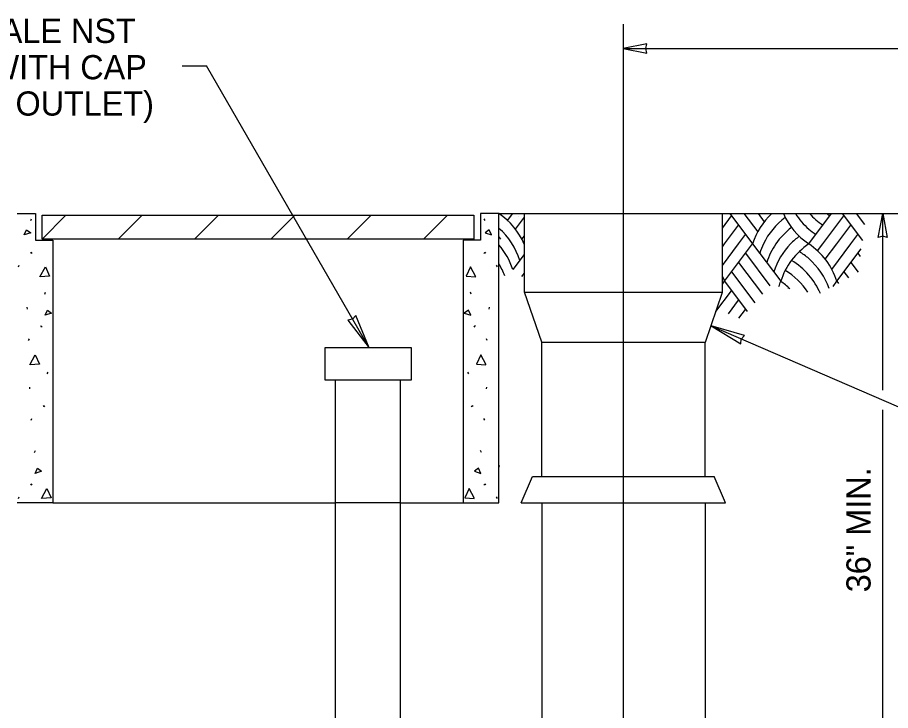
# Model space of a CAD drawing. Extents: x 99862 to 103151, y 99999 to 102075.
# Drawn here: x 100383 to 100960, y 100610 to 101068 of the extents above; entities that cross this region are included whole.
import ezdxf

# ---------------------------------------------------------------- set-up
doc = ezdxf.new("R2010")
doc.units = 0
for name, color, linetype in [('Level 1', 7, 'Continuous'), ('Level 10', 7, 'Continuous'), ('Level 13', 7, 'Continuous'), ('Level 15', 7, 'Continuous'), ('Level 17', 7, 'Continuous'), ('Level 18', 7, 'Continuous'), ('Level 20', 7, 'Continuous'), ('Level 3', 7, 'Continuous'), ('Level 6', 7, 'Continuous')]:
    doc.layers.add(name, color=color, linetype=linetype)

msp = doc.modelspace()

# ---------------------------------------------------------------- linework, layer by layer
at = {"layer": 'Level 1'}
for p, q in [((100391.62, 100933.79), (100392.18, 100935.05)), ((100399.05, 100921.6), (100399.05, 100937.39)), ((100399.05, 100937.39), (100684.58, 100937.39)), ((100684.58, 100937.39), (100684.58, 100921.6)), ((100692.01, 100933.79), (100691.45, 100935.05)), ((100684.58, 100921.6), (100399.05, 100921.6)), ((100391.44, 100913.04), (100391.85, 100912.31)), ((100391.85, 100912.75), (100392.43, 100912.06)), ((100691.78, 100912.75), (100691.2, 100912.06)), ((100692.19, 100913.04), (100691.78, 100912.31)), ((100383.49, 100903.21), (100384.05, 100904.35)), ((100700.14, 100903.21), (100699.58, 100904.35)), ((100400.83, 100885.19), (100401.39, 100886.45)), ((100682.8, 100885.19), (100682.24, 100886.45)), ((100389.04, 100876.54), (100389.2, 100875.4)), ((100694.59, 100876.54), (100694.43, 100875.4)), ((100398.14, 100864.44), (100398.55, 100863.71)), ((100398.55, 100864.15), (100399.11, 100863.46)), ((100685.08, 100864.15), (100684.51, 100863.46)), ((100685.49, 100864.44), (100685.08, 100863.71)), ((100390.18, 100854.62), (100390.75, 100855.75)), ((100693.45, 100854.62), (100692.88, 100855.75)), ((100402.49, 100832.51), (100403.06, 100833.77)), ((100681.14, 100832.51), (100680.56, 100833.77)), ((100390.71, 100823.86), (100390.88, 100822.72)), ((100692.91, 100823.86), (100692.75, 100822.72)), ((100399.81, 100811.76), (100400.23, 100811.04)), ((100683.81, 100811.76), (100683.4, 100811.04)), ((100400.23, 100811.49), (100400.79, 100810.79)), ((100683.4, 100811.49), (100682.84, 100810.79)), ((100391.85, 100801.95), (100392.43, 100803.09)), ((100691.78, 100801.95), (100691.2, 100803.09)), ((100394.13, 100780.7), (100394.69, 100781.96)), ((100689.5, 100780.7), (100688.94, 100781.96)), ((100701.28, 100772.05), (100701.13, 100770.91)), ((100391.44, 100759.95), (100391.85, 100759.22)), ((100692.19, 100759.95), (100691.78, 100759.22)), ((100391.85, 100759.66), (100392.43, 100758.97)), ((100691.78, 100759.66), (100691.2, 100758.97)), ((100383.49, 100750.12), (100384.05, 100751.26)), ((100700.14, 100750.12), (100699.58, 100751.26))]:
    msp.add_line(p, q, dxfattribs=at)
for points in [[(100387.35, 100924.35), (100388.9, 100927.75), (100391.59, 100925.76), (100387.35, 100924.35)], [(100696.28, 100924.35), (100694.73, 100927.75), (100692.04, 100925.76), (100696.28, 100924.35)], [(100397.69, 100896.71), (100401.26, 100903.37), (100404.1, 100897.12), (100397.85, 100896.71)], [(100685.94, 100896.71), (100682.36, 100903.37), (100679.53, 100897.12), (100685.78, 100896.71)], [(100401.14, 100871.26), (100402.69, 100874.67), (100405.36, 100872.69), (100401.14, 100871.26)], [(100682.49, 100871.26), (100680.94, 100874.67), (100678.26, 100872.69), (100682.49, 100871.26)], [(100391, 100838.49), (100394.56, 100845.15), (100397.41, 100838.89), (100391.16, 100838.49)], [(100692.63, 100838.49), (100689.06, 100845.15), (100686.21, 100838.89), (100692.46, 100838.49)], [(100394.44, 100766.77), (100395.99, 100770.17), (100398.68, 100768.19), (100394.44, 100766.77)], [(100689.19, 100766.77), (100687.64, 100770.17), (100684.95, 100768.19), (100689.19, 100766.77)], [(100398.68, 100750.12), (100402.25, 100756.79), (100405.09, 100750.54), (100398.84, 100750.12)], [(100684.95, 100750.12), (100681.38, 100756.79), (100678.54, 100750.54), (100684.79, 100750.12)]]:
    msp.add_lwpolyline(points, dxfattribs=at)
at = {"layer": 'Level 10'}
for p, q in [((100714.2, 100936.5), (100714.2, 100936.5)), ((100701.09, 100916.92), (100701.09, 100916.92))]:
    msp.add_line(p, q, dxfattribs=at)
at = {"layer": 'Level 13'}
for p, q in [((100848.88, 100928.91), (100854.96, 100937.02)), ((100853.87, 100938.46), (100868.88, 100918.46)), ((100863.15, 100938.46), (100872.22, 100926.37)), ((100872.44, 100938.46), (100876.53, 100933.01)), ((100906, 100918.46), (100921.01, 100938.46)), ((100915.28, 100918.46), (100929.21, 100937.02)), ((100928.12, 100938.46), (100941.45, 100920.69)), ((100937.4, 100938.46), (100942.85, 100931.2)), ((100850.32, 100918.46), (100859.6, 100930.83)), ((100924.57, 100918.46), (100933.85, 100930.83)), ((100859.6, 100918.46), (100864.24, 100924.64)), ((100933.85, 100918.46), (100938.49, 100924.64)), ((100848.88, 100916.53), (100850.32, 100918.45)), ((100848.88, 100904.16), (100859.6, 100918.45)), ((100850.32, 100893.71), (100868.88, 100918.45)), ((100868.88, 100918.45), (100887.44, 100893.71)), ((100911.82, 100913.84), (100915.28, 100918.45)), ((100916.92, 100908.26), (100924.57, 100918.45)), ((100921.22, 100901.62), (100933.85, 100918.45)), ((100864.24, 100912.27), (100880.32, 100890.83)), ((100924.57, 100893.71), (100940.72, 100915.25)), ((100938.49, 100912.27), (100940.05, 100910.18)), ((100859.6, 100906.08), (100875.3, 100885.15)), ((100933.85, 100906.08), (100938.65, 100899.68)), ((100854.96, 100899.89), (100870.27, 100879.47)), ((100929.21, 100899.89), (100932.16, 100895.95)), ((100848.88, 100891.78), (100850.32, 100893.71)), ((100850.32, 100893.71), (100865.25, 100873.8)), ((100922.07, 100890.38), (100924.57, 100893.71)), ((100924.57, 100893.71), (100925.6, 100892.33)), ((100844.57, 100873.67), (100854.96, 100887.52)), ((100852.84, 100872.32), (100859.6, 100881.33)), ((100859.85, 100869.3), (100864.24, 100875.14)), ((100841.39, 100864.19), (101030.06, 100782.83))]:
    msp.add_line(p, q, dxfattribs=at)
msp.add_lwpolyline([(100841.39, 100864.19), (100861.17, 100852.41), (100861.38, 100855.57), (100863.53, 100857.89)], close=True, dxfattribs=at)
for centre, start, end in [((100913.64, 100904.22), 133.19502, 162.3566), ((100918.28, 100898.03), 126.30625, 154.2266), ((100932.2, 100957.44), 203.83104, 236.09639), ((100936.84, 100963.63), 212.39562, 228.95992), ((100941.49, 100969.82), 221.87314, 236.09639), ((100946.13, 100976), 233.05424, 236.09639), ((100922.92, 100891.84), 127.1006, 145.49109), ((100936.84, 100963.63), 228.95986, 236.09639), ((100927.56, 100885.66), 126.331, 135.71278), ((100918.28, 100898.03), 154.22654, 162.3566), ((100922.92, 100891.84), 145.49102, 162.3566), ((100927.56, 100885.66), 135.71269, 162.3566), ((100932.2, 100879.47), 123.90361, 162.3566), ((100879.8, 100879.47), 17.6434, 56.09634), ((100875.16, 100873.28), 48.95968, 58.54646), ((100870.52, 100867.09), 40.94134, 59.30215), ((100875.16, 100873.28), 19.46417, 48.95975), ((100865.88, 100860.91), 33.00314, 58.48737), ((100805.56, 100879.47), 17.6434, 22.74071), ((100842.68, 100907.94), 337.94432, 342.3566), ((100861.24, 100854.72), 46.58948, 56.09639), ((100870.52, 100867.09), 23.37175, 40.94141), ((100847.32, 100901.75), 344.29333, 345.01126)]:
    msp.add_arc(centre, 46.97, start, end, dxfattribs=at)
at = {"layer": 'Level 15'}
for p, q in [((100783.25, 101063.64), (100783.25, 100327.05)), ((100783.25, 101047.64), (101637.9, 101047.64)), ((100491.77, 101036.06), (100507.77, 101036.06)), ((100615.3, 100849.81), (100507.77, 101036.06)), ((100701.48, 100938.46), (100717.93, 100938.46)), ((100848.88, 100938.46), (101864.1, 100938.46)), ((100954.84, 100821.8), (100954.84, 100938.46)), ((100954.84, 100520.56), (100954.84, 100808.73))]:
    msp.add_line(p, q, dxfattribs=at)
for points in [[(100783.25, 101047.64), (100798.98, 101044.56), (100798.25, 101047.64), (100798.98, 101050.73)], [(100954.84, 100938.46), (100957.92, 100922.74), (100954.84, 100923.47), (100951.75, 100922.74)], [(100615.3, 100849.81), (100606.47, 100871.08), (100604.41, 100868.67), (100601.3, 100868.09)]]:
    msp.add_lwpolyline(points, close=True, dxfattribs=at)
at = {"layer": 'Level 17'}
for p, q in [((100382.54, 100938.46), (100394.73, 100938.46)), ((100394.73, 100938.46), (100394.73, 100920.86)), ((100399.05, 100921.6), (100414.84, 100937.39)), ((100449.48, 100921.6), (100465.28, 100937.39)), ((100499.94, 100921.6), (100515.73, 100937.39)), ((100550.4, 100921.6), (100566.19, 100937.39)), ((100600.8, 100921.6), (100616.59, 100937.39)), ((100651.26, 100921.6), (100667.05, 100937.39)), ((100701.06, 100938.46), (100688.9, 100938.46)), ((100688.9, 100938.46), (100688.9, 100920.86)), ((100701.06, 100747.25), (100701.06, 100938.46)), ((100394.73, 100920.86), (100406.19, 100920.86)), ((100406.19, 100920.86), (100406.19, 100747.25)), ((100688.9, 100920.86), (100677.41, 100920.86)), ((100677.41, 100920.86), (100677.41, 100747.25)), ((100406.19, 100747.25), (100382.54, 100747.25)), ((100406.19, 100747.25), (100593.13, 100747.25)), ((100636.16, 100747.25), (100593.13, 100747.25)), ((100636.16, 100747.25), (100677.41, 100747.25)), ((100677.41, 100747.25), (100701.06, 100747.25))]:
    msp.add_line(p, q, dxfattribs=at)
at = {"layer": 'Level 18'}
for p, q in [((100717.93, 100938.46), (100848.88, 100938.46)), ((100717.93, 100886.47), (100717.93, 100938.46)), ((100848.88, 100886.47), (100848.88, 100938.46)), ((100717.93, 100886.47), (100848.88, 100886.47)), ((100729.45, 100853.41), (100717.93, 100886.47)), ((100837.76, 100853.41), (100848.88, 100886.47)), ((100729.45, 100853.41), (100837.76, 100853.41)), ((100729.45, 100764.81), (100729.45, 100853.41)), ((100837.38, 100764.81), (100837.38, 100853.41)), ((100715.78, 100747.25), (100723.33, 100764.81)), ((100723.33, 100764.81), (100843.48, 100764.81)), ((100851.03, 100747.25), (100843.48, 100764.81)), ((100715.78, 100747.25), (100851.03, 100747.25)), ((100729.45, 100747.25), (100729.45, 100567.2)), ((100837.38, 100747.25), (100837.38, 100567.2))]:
    msp.add_line(p, q, dxfattribs=at)
at = {"layer": 'Level 20'}
for p, q in [((100706.88, 100933.84), (100710.34, 100938.46)), ((100711.98, 100928.27), (100717.93, 100936.2)), ((100702.41, 100921.63), (100701.09, 100923.39)), ((100716.28, 100921.63), (100717.93, 100923.82)), ((100710.55, 100901.61), (100717.93, 100911.45)), ((100716.28, 100896.89), (100717.93, 100899.07))]:
    msp.add_line(p, q, dxfattribs=at)
for centre, start, end in [((100727.26, 100899.48), 123.90361, 123.9045), ((100674.86, 100899.48), 56.0955, 56.09634), ((100674.86, 100899.48), 23.53699, 56.0955), ((100670.22, 100893.29), 48.95968, 48.96107), ((100670.22, 100893.29), 17.6434, 48.95911), ((100665.58, 100887.1), 40.94134, 40.9433), ((100665.58, 100887.1), 17.75976, 40.94104), ((100660.94, 100880.92), 31.33163, 31.33464), ((100660.94, 100880.92), 20.4015, 31.33172)]:
    msp.add_arc(centre, 46.97, start, end, dxfattribs=at)
at = {"layer": 'Level 3'}
msp.add_line((100783.25, 100936.31), (100783.25, 100936.31), dxfattribs=at)
at = {"layer": 'Level 6'}
for p, q in [((100643.34, 100849.81), (100585.93, 100849.81)), ((100585.93, 100849.81), (100585.93, 100828.69)), ((100643.34, 100828.69), (100643.34, 100849.81)), ((100585.93, 100828.69), (100643.34, 100828.69)), ((100593.13, 100436.94), (100593.13, 100828.69)), ((100636.16, 100436.94), (100636.16, 100828.69))]:
    msp.add_line(p, q, dxfattribs=at)

# ---------------------------------------------------------------- texts
at = {"layer": 'Level 20'}
for s, p in [('2" FEMALE × IP × 2 1/2" MALE NST', (100112.84, 101051.2)), ('HOSE CONNECTION WITH CAP', (100147.4, 101027.2)), ('(BLOWOFF OUTLET)', (100262.67, 101003.2))]:
    msp.add_text(s, height=16, dxfattribs=at).set_placement(p)
msp.add_text('36" MIN.', height=16, rotation=90, dxfattribs=at).set_placement((100946.84, 100688.22))

doc.saveas('drawing.dxf')
